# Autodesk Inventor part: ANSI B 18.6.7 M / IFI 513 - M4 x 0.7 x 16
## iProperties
Comments: To add or edit properties for Autodesk Inventor files, use iProperties.
Created: 2004-08
Part Number: ANSI B 18.6.7 M / IFI 513 - M4 x 0.7 x 16
Vendor: Autodesk Inc.
Document SubType Name: Modeling
Designer: John Blackburn
Material: Default
Description: Trimmed Hex Head Machine Screw
Standard: ANSI B 18.6.7 M / IFI 513
Alert: To add or edit properties for Autodesk Inventor files, use iProperties.
Control State: 0
Master: False
Checked Out: False
Shininess: 64.0
Length Units: 11269
Angle Units: 11279
Time Units: 11290
Mass Units: 11283
Length Display Precision: 3
Angle Display Precision: 2
Compacted: True
EGR: 1
Classification: un/spsc 31161513
Density: 0.0
Volumn: 0.0
Area: 0.0
PropertySet Name: Model Information
Author: John Blackburn
Revision Number: 8
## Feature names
1. Body [Revolution]
2. Head [Extrusion]
3. Indent [Extrusion]
4. Chamfer1 [Revolution]
5. Chamfer2
